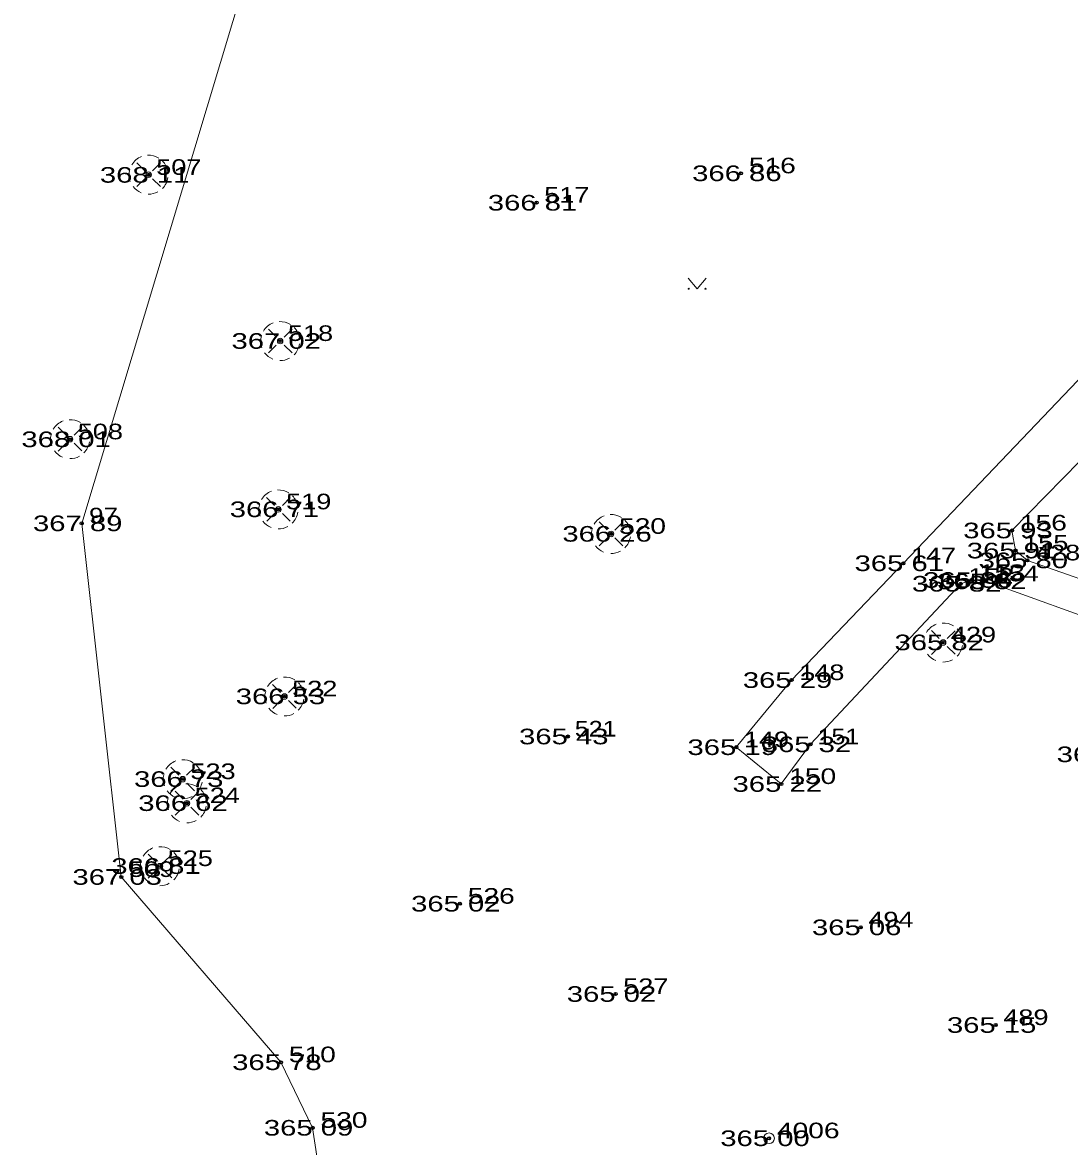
# Model space of a CAD drawing. Extents: x -789669 to -789458, y -977587 to -977420.
# Drawn here: x -789669.4 to -789622.4, y -977530.3 to -977479.9 of the extents above; entities that cross this region are included whole.
import ezdxf
from ezdxf.enums import TextEntityAlignment as Align

# ---------------------------------------------------------------- set-up
doc = ezdxf.new("R2010")
doc.units = 0
doc.header["$LTSCALE"] = 0.28
doc.header["$PDMODE"] = 32
doc.header["$PDSIZE"] = 0.14
for name, color, linetype, lineweight in [('1', 7, 'Continuous', 13), ('3', 7, 'Continuous', 13), ('4', 7, 'Continuous', 13), ('50', 7, 'Continuous', 13)]:
    doc.layers.add(name, color=color, linetype=linetype, lineweight=lineweight)
for name, color, linetype in [('57', 7, 'Continuous'), ('58', 7, 'Continuous'), ('59', 7, 'Continuous')]:
    doc.layers.add(name, color=color, linetype=linetype)

msp = doc.modelspace()

# ---------------------------------------------------------------- linework, layer by layer
at = {"layer": '1'}
msp.add_line((-789637.37, -977512.43), (-789635.35, -977514.08), dxfattribs=at)
for points in [[(-789601.64, -977464.89), (-789599.95, -977466.17), (-789598.64, -977467.75), (-789598.59, -977469.78), (-789599.16, -977471.77), (-789600.59, -977473.55), (-789609.94, -977483.26), (-789619.88, -977493.69), (-789629.88, -977504.18), (-789634.89, -977509.42), (-789637.37, -977512.43)], [(-789624.85, -977503.61), (-789625.01, -977502.71), (-789618.92, -977496.49), (-789609.22, -977486.14), (-789603.75, -977480.49), (-789602.26, -977483.1), (-789598.63, -977486.58)], [(-789624.85, -977503.61), (-789624.32, -977504.05), (-789615.44, -977507.16), (-789606.39, -977510.56)], [(-789635.35, -977514.08), (-789634.04, -977512.3), (-789627.31, -977505.1), (-789626.81, -977504.93), (-789626.18, -977504.99)], [(-789607.79, -977511.44), (-789616.25, -977508.57), (-789626.18, -977504.99)]]:
    msp.add_lwpolyline(points, dxfattribs=at)
at = {"layer": '3'}
for points in [[(-789666.71, -977502.39), (-789654.87, -977463.01), (-789641.19, -977459.01), (-789614.78, -977466.03), (-789608.83, -977467.57), (-789606.74, -977465.22)], [(-789655.43, -977535.64), (-789656.36, -977529.5), (-789657.78, -977526.56), (-789664.94, -977518.25), (-789666.71, -977502.39)]]:
    msp.add_lwpolyline(points, dxfattribs=at)
at = {"layer": '4'}
for p, q in [((-789664.244, -977486.216), (-789663.887, -977486.572)), ((-789663.184, -977486.224), (-789663.537, -977486.577)), ((-789664.24, -977487.287), (-789663.888, -977486.936)), ((-789663.71, -977486.76), (-789663.71, -977486.748)), ((-789663.536, -977486.931), (-789663.184, -977487.281)), ((-789658.344, -977493.678), (-789657.987, -977494.034)), ((-789657.284, -977493.686), (-789657.637, -977494.039)), ((-789657.81, -977494.222), (-789657.81, -977494.21)), ((-789658.34, -977494.749), (-789657.988, -977494.398)), ((-789657.636, -977494.393), (-789657.284, -977494.743)), ((-789667.764, -977498.076), (-789667.407, -977498.432)), ((-789666.704, -977498.084), (-789667.057, -977498.437)), ((-789667.76, -977499.147), (-789667.408, -977498.796)), ((-789667.23, -977498.62), (-789667.23, -977498.608)), ((-789667.056, -977498.791), (-789666.704, -977499.141)), ((-789658.424, -977501.228), (-789658.067, -977501.584)), ((-789657.364, -977501.236), (-789657.717, -977501.589)), ((-789657.89, -977501.772), (-789657.89, -977501.76)), ((-789658.42, -977502.299), (-789658.068, -977501.948)), ((-789657.716, -977501.943), (-789657.364, -977502.293)), ((-789643.514, -977502.328), (-789643.157, -977502.684)), ((-789642.454, -977502.336), (-789642.807, -977502.689)), ((-789642.98, -977502.872), (-789642.98, -977502.86)), ((-789643.51, -977503.399), (-789643.158, -977503.048)), ((-789642.806, -977503.043), (-789642.454, -977503.393)), ((-789628.624, -977507.198), (-789628.267, -977507.554)), ((-789627.564, -977507.206), (-789627.917, -977507.559)), ((-789628.09, -977507.742), (-789628.09, -977507.73)), ((-789627.916, -977507.913), (-789627.564, -977508.263)), ((-789628.62, -977508.269), (-789628.268, -977507.918)), ((-789658.154, -977509.618), (-789657.797, -977509.974)), ((-789657.094, -977509.626), (-789657.447, -977509.979)), ((-789658.15, -977510.689), (-789657.798, -977510.338)), ((-789657.62, -977510.162), (-789657.62, -977510.15)), ((-789657.446, -977510.333), (-789657.094, -977510.683)), ((-789662.714, -977513.328), (-789662.357, -977513.684)), ((-789661.654, -977513.336), (-789662.007, -977513.689)), ((-789662.18, -977513.872), (-789662.18, -977513.86)), ((-789662.71, -977514.399), (-789662.358, -977514.048)), ((-789662.524, -977514.408), (-789662.167, -977514.764)), ((-789662.006, -977514.043), (-789661.654, -977514.393)), ((-789661.464, -977514.416), (-789661.817, -977514.769)), ((-789661.99, -977514.952), (-789661.99, -977514.94)), ((-789662.52, -977515.479), (-789662.168, -977515.128)), ((-789661.816, -977515.123), (-789661.464, -977515.473)), ((-789663.734, -977517.228), (-789663.377, -977517.584)), ((-789662.674, -977517.236), (-789663.027, -977517.589)), ((-789663.73, -977518.299), (-789663.378, -977517.948)), ((-789663.2, -977517.772), (-789663.2, -977517.76)), ((-789663.026, -977517.943), (-789662.674, -977518.293))]:
    msp.add_line(p, q, dxfattribs=at)
for points in [[(-789639.528, -977491.389), (-789639.126, -977491.868), (-789638.724, -977491.389)], [(-789639.5, -977491.845), (-789639.486, -977491.853), (-789639.481, -977491.868), (-789639.487, -977491.881), (-789639.5, -977491.889), (-789639.516, -977491.881), (-789639.522, -977491.868), (-789639.518, -977491.854), (-789639.507, -977491.848), (-789639.492, -977491.854), (-789639.487, -977491.868), (-789639.49, -977491.878), (-789639.5, -977491.883), (-789639.511, -977491.878), (-789639.517, -977491.867), (-789639.512, -977491.857), (-789639.507, -977491.854), (-789639.496, -977491.858), (-789639.491, -977491.868), (-789639.497, -977491.875), (-789639.505, -977491.873), (-789639.51, -977491.865), (-789639.505, -977491.86), (-789639.497, -977491.864), (-789639.5, -977491.868)], [(-789638.75, -977491.846), (-789638.736, -977491.854), (-789638.731, -977491.869), (-789638.737, -977491.882), (-789638.75, -977491.89), (-789638.766, -977491.882), (-789638.772, -977491.869), (-789638.768, -977491.855), (-789638.757, -977491.849), (-789638.742, -977491.855), (-789638.737, -977491.869), (-789638.74, -977491.879), (-789638.75, -977491.884), (-789638.761, -977491.879), (-789638.767, -977491.868), (-789638.762, -977491.858), (-789638.757, -977491.855), (-789638.746, -977491.859), (-789638.741, -977491.869), (-789638.747, -977491.876), (-789638.755, -977491.874), (-789638.76, -977491.866), (-789638.755, -977491.861), (-789638.747, -977491.865), (-789638.75, -977491.869)]]:
    msp.add_lwpolyline(points, dxfattribs=at)
for centre, radius in [((-789663.7139, -977486.7534), 0.125), ((-789639.501, -977491.868), 0.025), ((-789638.751, -977491.868), 0.025), ((-789657.8139, -977494.2154), 0.125), ((-789667.2339, -977498.6134), 0.125), ((-789657.8939, -977501.7654), 0.125), ((-789642.9839, -977502.8654), 0.125), ((-789628.0939, -977507.7354), 0.125), ((-789657.6239, -977510.1554), 0.125), ((-789662.1839, -977513.8654), 0.125), ((-789661.9939, -977514.9454), 0.125), ((-789663.2039, -977517.7654), 0.125)]:
    msp.add_circle(centre, radius, dxfattribs=at)
for centre, start, end in [((-789663.7139, -977486.7534), 111.04924, 149.34666), ((-789663.7139, -977486.7534), 57.94289, 92.85253), ((-789663.7139, -977486.7534), 9.68453, 44.47714), ((-789663.7139, -977486.7534), 166.76695, 200.11735), ((-789663.7139, -977486.7534), 315.09105, 351.67435), ((-789663.7139, -977486.7534), 217.06959, 247.69959), ((-789663.7139, -977486.7534), 269.18965, 298.56841), ((-789657.8139, -977494.2154), 111.04924, 149.34666), ((-789657.8139, -977494.2154), 57.94289, 92.85253), ((-789657.8139, -977494.2154), 9.68453, 44.47714), ((-789657.8139, -977494.2154), 166.76695, 200.11735), ((-789657.8139, -977494.2154), 217.06959, 247.69959), ((-789657.8139, -977494.2154), 315.09105, 351.67435), ((-789657.8139, -977494.2154), 269.18965, 298.56841), ((-789667.2339, -977498.6134), 111.04924, 149.34666), ((-789667.2339, -977498.6134), 57.94289, 92.85253), ((-789667.2339, -977498.6134), 9.68453, 44.47714), ((-789667.2339, -977498.6134), 166.76695, 200.11735), ((-789667.2339, -977498.6134), 315.09105, 351.67435), ((-789667.2339, -977498.6134), 217.06959, 247.69959), ((-789667.2339, -977498.6134), 269.18965, 298.56841), ((-789657.8939, -977501.7654), 111.04924, 149.34666), ((-789657.8939, -977501.7654), 57.94289, 92.85253), ((-789657.8939, -977501.7654), 9.68453, 44.47714), ((-789657.8939, -977501.7654), 166.76695, 200.11735), ((-789657.8939, -977501.7654), 217.06959, 247.69959), ((-789657.8939, -977501.7654), 315.09105, 351.67435), ((-789642.9839, -977502.8654), 111.04924, 149.34666), ((-789642.9839, -977502.8654), 57.94289, 92.85253), ((-789642.9839, -977502.8654), 9.68453, 44.47714), ((-789657.8939, -977501.7654), 269.18965, 298.56841), ((-789642.9839, -977502.8654), 166.76695, 200.11735), ((-789642.9839, -977502.8654), 315.09105, 351.67435), ((-789642.9839, -977502.8654), 217.06959, 247.69959), ((-789642.9839, -977502.8654), 269.18965, 298.56841), ((-789628.0939, -977507.7354), 57.94289, 92.85253), ((-789628.0939, -977507.7354), 111.04924, 149.34666), ((-789628.0939, -977507.7354), 9.68453, 44.47714), ((-789628.0939, -977507.7354), 166.76695, 200.11735), ((-789628.0939, -977507.7354), 315.09105, 351.67435), ((-789628.0939, -977507.7354), 217.06959, 247.69959), ((-789628.0939, -977507.7354), 269.18965, 298.56841), ((-789657.6239, -977510.1554), 111.04924, 149.34666), ((-789657.6239, -977510.1554), 57.94289, 92.85253), ((-789657.6239, -977510.1554), 9.68453, 44.47714), ((-789657.6239, -977510.1554), 166.76695, 200.11735), ((-789657.6239, -977510.1554), 315.09105, 351.67435), ((-789657.6239, -977510.1554), 217.06959, 247.69959), ((-789657.6239, -977510.1554), 269.18965, 298.56841), ((-789662.1839, -977513.8654), 111.04924, 149.34666), ((-789662.1839, -977513.8654), 57.94289, 92.85253), ((-789662.1839, -977513.8654), 9.68453, 44.47714), ((-789662.1839, -977513.8654), 166.76695, 200.11735), ((-789662.1839, -977513.8654), 217.06959, 247.69959), ((-789661.9939, -977514.9454), 111.04924, 149.34666), ((-789661.9939, -977514.9454), 57.94289, 92.85253), ((-789662.1839, -977513.8654), 315.09105, 351.67435), ((-789661.9939, -977514.9454), 9.68453, 44.47714), ((-789661.9939, -977514.9454), 166.76695, 200.11735), ((-789662.1839, -977513.8654), 269.18965, 298.56841), ((-789661.9939, -977514.9454), 217.06959, 247.69959), ((-789661.9939, -977514.9454), 315.09105, 351.67435), ((-789661.9939, -977514.9454), 269.18965, 298.56841), ((-789663.2039, -977517.7654), 111.04924, 149.34666), ((-789663.2039, -977517.7654), 57.94289, 92.85253), ((-789663.2039, -977517.7654), 9.68453, 44.47714), ((-789663.2039, -977517.7654), 166.76695, 200.11735), ((-789663.2039, -977517.7654), 315.09105, 351.67435), ((-789663.2039, -977517.7654), 217.06959, 247.69959), ((-789663.2039, -977517.7654), 269.18965, 298.56841)]:
    msp.add_arc(centre, 0.875, start, end, dxfattribs=at)
at = {"layer": '50'}
msp.add_line((-789635.908, -977529.97), (-789635.892, -977529.97), dxfattribs=at)
msp.add_circle((-789635.8998, -977529.9705), 0.24, dxfattribs=at)
at = {"layer": '57'}
for p in [(-789663.71, -977486.76), (-789637.16, -977486.69), (-789646.32, -977488.01), (-789657.81, -977494.21), (-789667.23, -977498.62), (-789657.89, -977501.76), (-789666.71, -977502.39), (-789642.98, -977502.86), (-789625.01, -977502.71), (-789624.85, -977503.61), (-789629.88, -977504.18), (-789624.32, -977504.05), (-789626.81, -977504.93), (-789627.31, -977505.1), (-789626.18, -977504.99), (-789628.09, -977507.73), (-789634.89, -977509.42), (-789657.62, -977510.15), (-789644.92, -977511.95), (-789637.37, -977512.43), (-789634.04, -977512.3), (-789662.18, -977513.86), (-789635.35, -977514.08), (-789661.99, -977514.94), (-789663.2, -977517.76), (-789664.94, -977518.25), (-789649.76, -977519.45), (-789631.79, -977520.51), (-789642.78, -977523.5), (-789625.74, -977524.89), (-789657.78, -977526.56), (-789656.36, -977529.5), (-789635.9, -977529.97)]:
    msp.add_point(p, dxfattribs=at)

# ---------------------------------------------------------------- texts
at = {"layer": '50', "width": 1.35}
msp.add_text(' 4006', height=0.7, dxfattribs=at).set_placement((-789635.9, -977529.97))
at = {"layer": '58'}
for s, width, p in [(' 507', 1.3, (-789663.71, -977486.76)), (' 516', 1.35, (-789637.16, -977486.69)), (' 517', 1.3, (-789646.32, -977488.01)), (' 518', 1.3, (-789657.81, -977494.21)), (' 508', 1.3, (-789667.23, -977498.62)), (' 519', 1.3, (-789657.89, -977501.76)), (' 97', 1.25, (-789666.71, -977502.39)), (' 520', 1.35, (-789642.98, -977502.86)), (' 156', 1.35, (-789625.01, -977502.71)), (' 155', 1.3, (-789624.85, -977503.61)), (' 428', 1.3, (-789624.32, -977504.05)), (' 147', 1.3, (-789629.88, -977504.18)), (' 153', 1.3, (-789626.81, -977504.93)), (' 154', 1.3, (-789626.18, -977504.99)), (' 152', 1.3, (-789627.31, -977505.1)), (' 429', 1.3, (-789628.09, -977507.73)), (' 148', 1.3, (-789634.89, -977509.42)), (' 522', 1.3, (-789657.62, -977510.15)), (' 521', 1.2, (-789644.92, -977511.95)), (' 149', 1.3, (-789637.37, -977512.43)), (' 151', 1.2, (-789634.04, -977512.3)), (' 523', 1.3, (-789662.18, -977513.86)), (' 150', 1.35, (-789635.35, -977514.08)), (' 524', 1.3, (-789661.99, -977514.94)), (' 525', 1.3, (-789663.2, -977517.76)), (' 509', 1.3, (-789664.94, -977518.25)), (' 526', 1.35, (-789649.76, -977519.45)), (' 494', 1.3, (-789631.79, -977520.51)), (' 527', 1.3, (-789642.78, -977523.5)), (' 489', 1.3, (-789625.74, -977524.89)), (' 510', 1.35, (-789657.78, -977526.56)), (' 530', 1.35, (-789656.36, -977529.5)), (' 4006', 1.35, (-789635.9, -977529.97))]:
    msp.add_text(s, height=0.7, dxfattribs=dict(at, width=width)).set_placement(p)
at = {"layer": '59', "width": 1.4}
for s, p in [('368 11 ', (-789663.71, -977487.11)), ('366 86 ', (-789637.16, -977487.04)), ('366 81 ', (-789646.32, -977488.36)), ('367 02 ', (-789657.81, -977494.56)), ('368 01 ', (-789667.23, -977498.97)), ('366 71 ', (-789657.89, -977502.11)), ('367 89 ', (-789666.71, -977502.74)), ('365 93 ', (-789625.01, -977503.06)), ('366 26 ', (-789642.98, -977503.21)), ('365 91 ', (-789624.85, -977503.96)), ('365 61 ', (-789629.88, -977504.53)), ('365 80 ', (-789624.32, -977504.4)), ('365 82 ', (-789627.31, -977505.45)), ('365 86 ', (-789626.81, -977505.28)), ('365 82 ', (-789626.18, -977505.34)), ('365 82 ', (-789628.09, -977508.08)), ('365 29 ', (-789634.89, -977509.77)), ('366 53 ', (-789657.62, -977510.5)), ('365 43 ', (-789644.92, -977512.3)), ('365 32 ', (-789634.04, -977512.65)), ('365 19 ', (-789637.37, -977512.78)), ('365 41 ', (-789620.82, -977513.1)), ('366 73 ', (-789662.18, -977514.21)), ('365 22 ', (-789635.35, -977514.43)), ('366 62 ', (-789661.99, -977515.29)), ('366 81 ', (-789663.2, -977518.11)), ('367 03 ', (-789664.94, -977518.6)), ('365 02 ', (-789649.76, -977519.8)), ('365 06 ', (-789631.79, -977520.86)), ('365 02 ', (-789642.78, -977523.85)), ('365 15 ', (-789625.74, -977525.24)), ('365 78 ', (-789657.78, -977526.91)), ('365 09 ', (-789656.36, -977529.85)), ('365 00 ', (-789635.9, -977530.32))]:
    msp.add_text(s, height=0.7, dxfattribs=at).set_placement(p, align=Align.CENTER)

doc.saveas('drawing.dxf')
